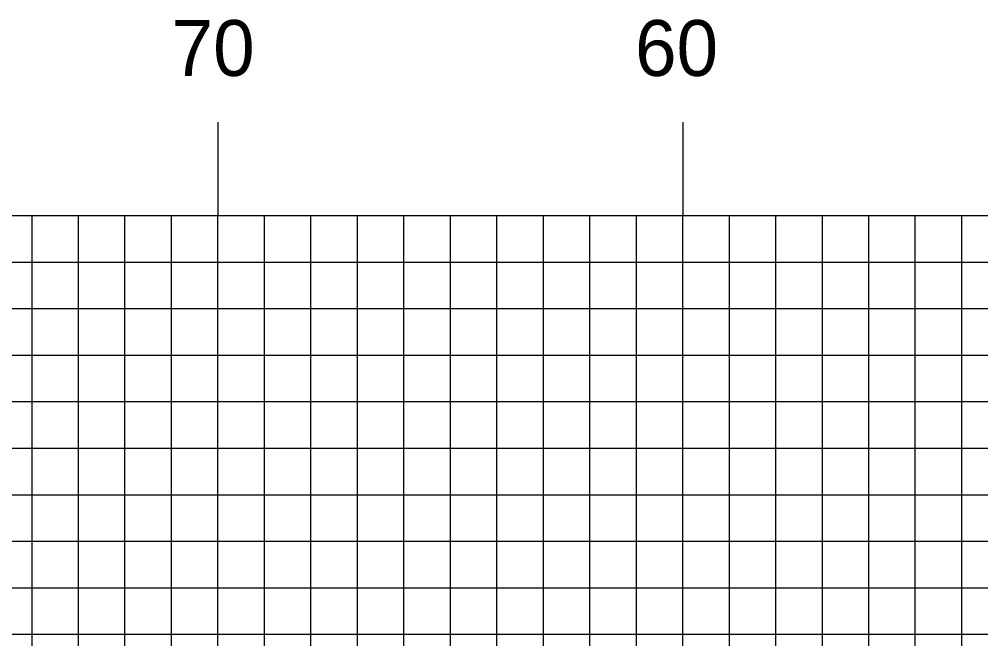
# Model space of a CAD drawing. Extents: x 1769661 to 1770005, y 442591 to 442811.
# Drawn here: x 1769752.74 to 1769773.42, y 442724.57 to 442737.88 of the extents above; entities that cross this region are included whole.
import ezdxf

# ---------------------------------------------------------------- set-up
doc = ezdxf.new("R2010")
doc.units = 0
for name, color, linetype in [('H_V ANNOTATION', 7, 'Continuous'), ('MAJOR', 7, 'Continuous'), ('MINOR', 7, 'Continuous')]:
    doc.layers.add(name, color=color, linetype=linetype)

msp = doc.modelspace()

# ---------------------------------------------------------------- linework, layer by layer
at = {"layer": 'MAJOR'}
for p, q in [((1769757.015, 442735.669), (1769757.015, 442733.665)), ((1769767.015, 442735.669), (1769767.015, 442733.665)), ((1769687.015, 442733.665), (1769967.015, 442733.665)), ((1769687.015, 442733.665), (1769967.015, 442733.665)), ((1769757.015, 442678.665), (1769757.015, 442733.665)), ((1769767.015, 442678.665), (1769767.015, 442733.665)), ((1769687.015, 442728.665), (1769967.015, 442728.665))]:
    msp.add_line(p, q, dxfattribs=at)
at = {"layer": 'MINOR'}
for p, q in [((1769753.015, 442678.665), (1769753.015, 442733.665)), ((1769754.015, 442678.665), (1769754.015, 442733.665)), ((1769755.015, 442678.665), (1769755.015, 442733.665)), ((1769756.015, 442678.665), (1769756.015, 442733.665)), ((1769758.015, 442678.665), (1769758.015, 442733.665)), ((1769759.015, 442678.665), (1769759.015, 442733.665)), ((1769760.015, 442678.665), (1769760.015, 442733.665)), ((1769761.015, 442678.665), (1769761.015, 442733.665)), ((1769762.015, 442678.665), (1769762.015, 442733.665)), ((1769763.015, 442678.665), (1769763.015, 442733.665)), ((1769764.015, 442678.665), (1769764.015, 442733.665)), ((1769765.015, 442678.665), (1769765.015, 442733.665)), ((1769766.015, 442678.665), (1769766.015, 442733.665)), ((1769768.015, 442678.665), (1769768.015, 442733.665)), ((1769769.015, 442678.665), (1769769.015, 442733.665)), ((1769770.015, 442678.665), (1769770.015, 442733.665)), ((1769771.015, 442678.665), (1769771.015, 442733.665)), ((1769772.015, 442678.665), (1769772.015, 442733.665)), ((1769773.015, 442678.665), (1769773.015, 442733.665)), ((1769687.015, 442732.665), (1769967.015, 442732.665)), ((1769687.015, 442731.665), (1769967.015, 442731.665)), ((1769687.015, 442730.665), (1769967.015, 442730.665)), ((1769687.015, 442729.665), (1769967.015, 442729.665)), ((1769687.015, 442727.665), (1769967.015, 442727.665)), ((1769687.015, 442726.665), (1769967.015, 442726.665)), ((1769687.015, 442725.665), (1769967.015, 442725.665)), ((1769687.015, 442724.665), (1769967.015, 442724.665))]:
    msp.add_line(p, q, dxfattribs=at)

# ---------------------------------------------------------------- texts
at = {"layer": 'H_V ANNOTATION'}
for s, p in [('70', (1769756.019, 442736.665)), ('60', (1769765.987, 442736.665))]:
    msp.add_text(s, height=1.2, dxfattribs=at).set_placement(p)

doc.saveas('drawing.dxf')
